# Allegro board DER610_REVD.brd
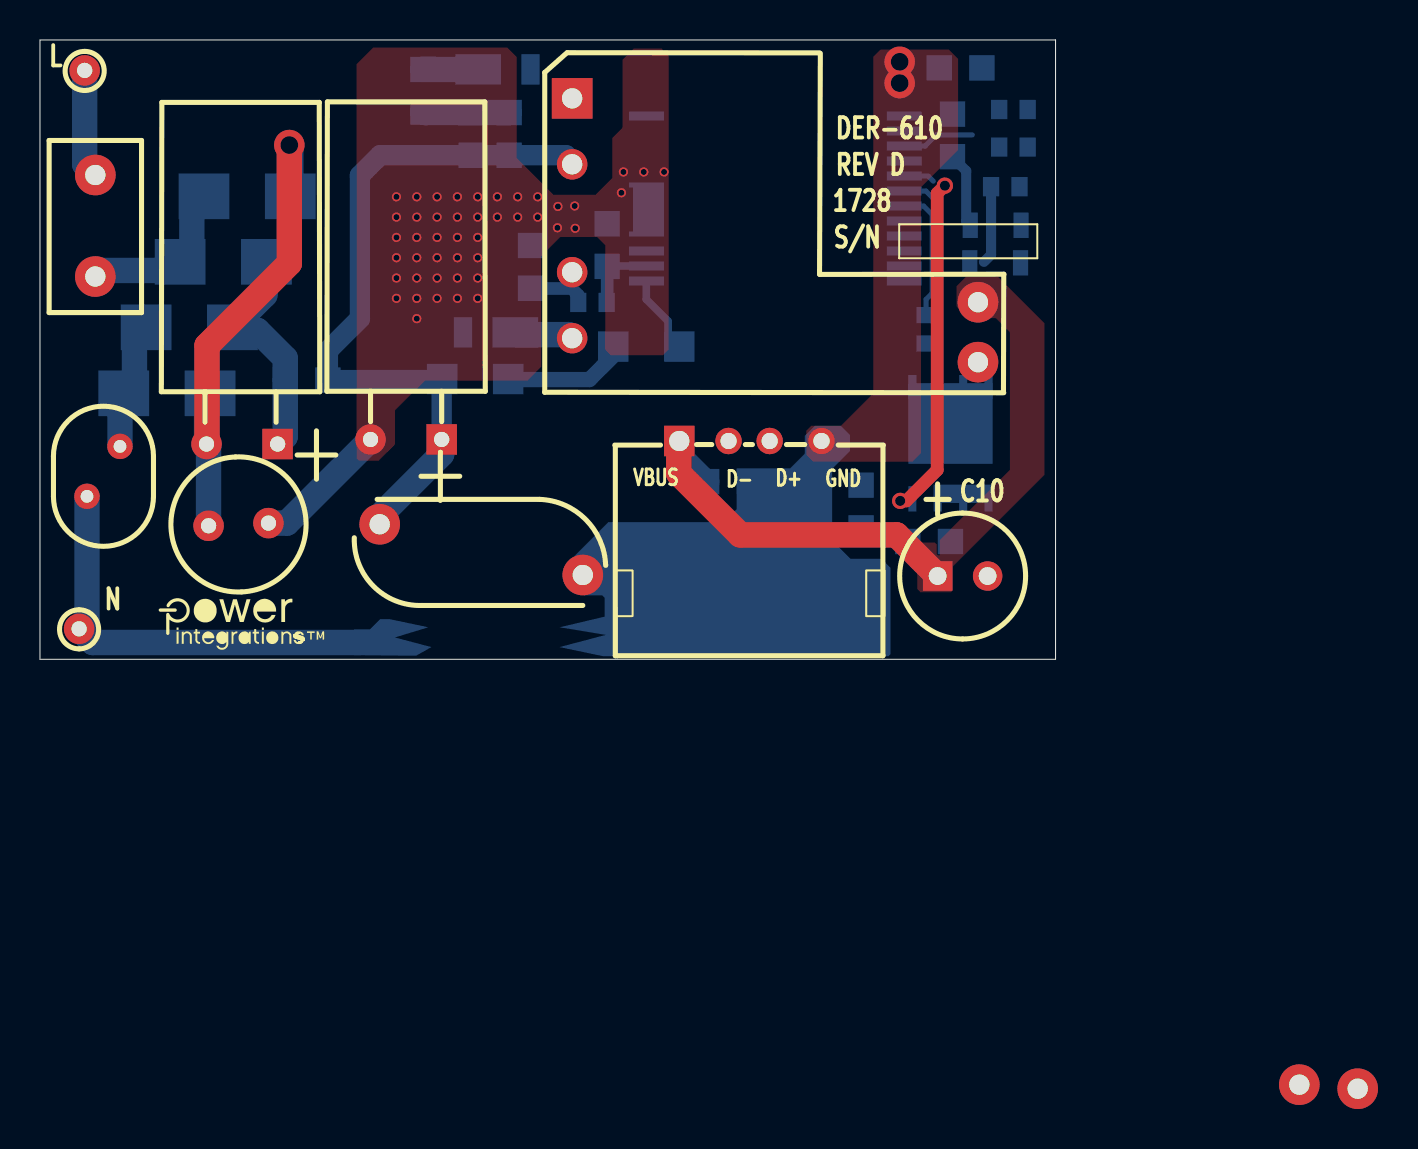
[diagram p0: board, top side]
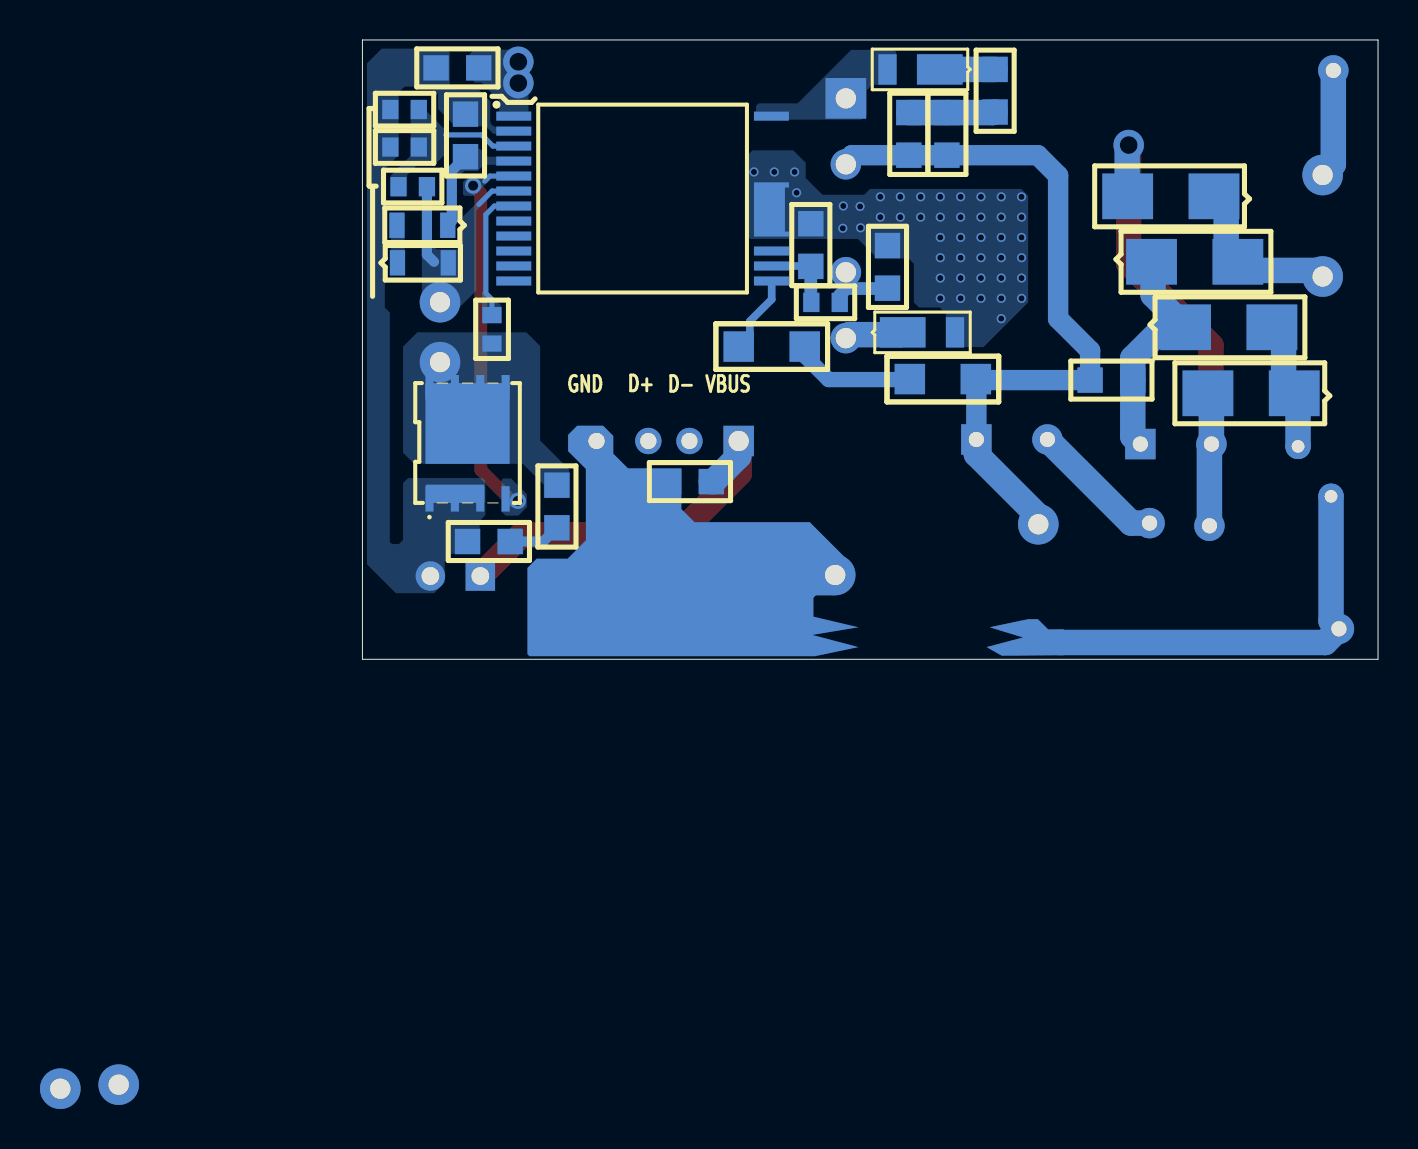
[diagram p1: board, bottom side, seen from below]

Outline 50.8 x 30.99 mm; copper layers: TOP, BOTTOM. Coordinates in mm from the lower left corner of the outline.
Outline path: 0,30.99 0,0 50.8,0 50.8,30.99 0,30.99

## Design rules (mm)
constraint set DEFAULT: min track width 0.508

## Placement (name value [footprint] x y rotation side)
C1  8.2 uF  [PIPOLCAPCLYD320LS140030]  10.11 10.77 180 top
C2  8.2 uF  [PIPOLCAPCLYD320LS140030]  18.31 11 180 bottom
C3  1 nF  [PISMC0805]  23.47 27.36 270 bottom
C4  22 uF  [PISMC0805]  24.54 18.57 90 bottom
C5  4.7 uF  [PISMC0805]  28.37 21.79 270 bottom
C6  2.2 uF  [PISMC0805]  45.64 27.28 270 bottom
C7  330 pF  [PISMC0603]  49.4 27.51 180 bottom
C8  100 pF  [PINPYCAPRAD500X220LS400040]  16.99 6.76 0 top
C9  1.5 nF  [PISMC0805]  43.41 5.89 0 bottom
C10  560 uF  [PI_POLCAP_D248LS098D035]  46.15 4.17 0 top
C12  1 uF  [PISMC0805]  33.35 8.89 0 bottom
D1  RS2MA-13-F  [PISMDO214AC12]  11.33 19.89 180 bottom
D2  RS2MA-13-F  [PISMDO214AC12]  9.63 16.61 180 bottom
D3  RS2MA-13-F  [PISMDO214AC12]  8.2 23.16 0 bottom
D4  RS2MA-13-F  [PISMDO214AC12]  4.19 13.31 0 bottom
D5  DFLR1600-7  [PISMDDFLR120012]  21.89 29.51 180 bottom
D6  DFLR1200-7  [PISMDDFLR120012]  23.8 16.36 0 bottom
D7  BAV19WS  [PISMSOD323]  49.05 19.84 180 bottom
D8  BAV19WS  [PISMSOD323]  46.53 21.72 0 bottom
F1  3.15 A  [PI_RST_MICROFUSE]  2.77 19.15 90 top
J1  PCB Terminal 30 AWG  [PI_HOLE_30AWG]  2.24 29.46 0 top
J2  PCB Terminal 30 AWG  [PI_HOLE_30AWG]  1.96 1.52 0 top
J3  CON4  [PI_USB_4P_GOLDCONN]  31.98 10.92 0 top
L1  4.7 uH  [PISMR0805]  12.27 13.97 0 bottom
L2  100 uH  [PI_CHOKE_365HX275LS118D030]  8.43 6.68 2.5 top
NOREF  -  []  -219.41 -144.7 0 top
NOREF#2  -  []  0.03 0.03 0 top
NOREF#3  -  []  5.38 2.95 0 top
NOREF#4  -  []  -141.59 54.31 0 top
NOREF#5  -  []  0.03 0.03 90 top
Q1  SI7370DP-T1-E3  [PISMPQFN5X6B]  47.45 8.03 180 bottom
R1  200 k  [PISMR0805]  21.56 27.36 270 bottom
R2  30  [PISMR0805]  19.15 29.51 270 bottom
R3  26.7 k  [PISMR0603]  26.92 17.86 0 bottom
R5  2.00 M  [PISMR1206]  31.98 15.65 180 bottom
R6  47  [PISMR0603]  44.32 15.8 90 bottom
R7  20  [PISMR0805]  41.07 6.58 90 bottom
R8  100 k  [PISMR0603]  47.57 23.65 0 bottom
R9  34 k  [PISMR0603]  47.98 25.63 0 bottom
R12  1.50 M  [PISMR1206]  20.12 14.02 0 bottom
R13  0.015  [PISMR0805]  44.98 29.59 0 bottom
RT1  10  [PI_RAD_276DX197T_LS100D025]  3.17 8.15 90 top
T1  EE1621  [PI_BOBBIN_EE1621_8P]  26.62 28.07 0 top
U1  INN3162C  [PI_IC_INSOP_24D]  43.23 27.18 180 bottom

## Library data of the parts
C1 C2 = CAP POL: alternate symbols: (pipolcapclyd320ls140030575h)
C3-C9 C12 = CAP NP
C10 = CAP POL
D1-D8 = DIODE
F1 = FUSE: alternate symbols: (pirstmicrofusehoz)
J1 J2 = TERM_1Pin
J3 = CON4_USB_1
L1 L2 = INDUCTOR
Q1 = FET_N_SGD_123_4_5678
R1-R3 R5-R9 R12 R13 = R
RT1 = THERMISTOR
T1 = BEE16_8P/GENERIC
U1 = DEV_Inno3CE

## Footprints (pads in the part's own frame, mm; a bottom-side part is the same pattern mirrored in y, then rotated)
PI_BOBBIN_EE1621_8P
  rect 2.032x2.032 hole 1.016: 1(0,0)
  round 1.524 hole 1.016: 2(0,-3.3) 3(0,-8.7) 4(0,-12)
  round 2.032 hole 1.016: 5(20.3,-13.2) 6(20.3,-10.2) 7(36.373,-49.352) 8(39.294,-49.555)
PI_CHOKE_365HX275LS118D030
  round 1.524 hole 0.762: 1(0,0) 2(2.997,0)
PI_HOLE_30AWG
  round 1.524 hole 0.762: 1(0,0)
PI_IC_INSOP_24D
  rect 1.75x0.45 smd: 1(0,0) 2(0,-0.75) 3(0,-1.5) 4(0,-2.25) 5(0,-3) 6(0,-3.75) 7(0,-4.5) 8(0,-5.25) 9(0,-6) 10(0,-6.75) 11(0,-7.5) 12(0,-8.25) 13(12.89,-8.25) 14(12.89,-7.5) 15(12.89,-6.75) 24(12.89,0)
  custom 0.438x0.438 smd: 16(12.89,-4.67)
PI_POLCAP_D248LS098D035
  rect 1.473x1.473 hole 0.889: 1(-1.25,0)
  round 1.473 hole 0.889: 2(1.25,0)
PI_RAD_276DX197T_LS100D025
  round 1.27 hole 0.635: 1(0,0.825) 2(2.5,-0.825)
PI_RST_MICROFUSE
  round 2.032 hole 1.016: 1(0,0) 2(5.08,0)
PI_USB_4P_GOLDCONN
  rect 1.524x1.524 hole 1.016: 1(0,0)
  round 1.321 hole 0.813: 2(2.464,0) 3(4.521,0) 4(7.112,0)
PINPYCAPRAD500X220LS400040
  round 2.032 hole 1.016: 1(0,0) 2(10.16,-2.54)
PIPOLCAPCLYD320LS140030
  rect 1.524x1.524 hole 0.762: 1(-1.778,0)
  round 1.524 hole 0.762: 2(1.778,0)
PISMC0603
  rect 0.813x0.965 smd: 1(0,0) 2(1.422,0)
PISMC0805
  rect 1.27x1.27 smd: 1(0,0) 2(2.134,0)
PISMDDFLR120012
  rect 2.286x1.524 smd: 1(-0.025,0)
  rect 0.914x1.524 smd: 2(-2.642,0)
PISMDO214AC12
  rect 2.54x2.286 smd: 1(0,0) 2(4.318,0)
PISMPQFN5X6B
  rect 0.406x1.27 smd: 1(0,0) 2(1.27,0) 3(2.54,0) 4(3.81,0)
  rect 0.406x1.219 smd: 5(3.81,5.588) 6(2.54,5.588) 7(1.27,5.588) 8(0,5.588)
PISMR0603
  rect 0.813x0.965 smd: 1(0,0) 2(1.422,0)
PISMR0805
  rect 1.27x1.27 smd: 1(0,0) 2(2.134,0)
PISMR1206
  rect 1.524x1.524 smd: 1(0,0) 2(3.302,0)
PISMSOD323
  rect 0.762x1.27 smd: 1(0,0) 2(2.54,0)

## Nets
D: Q1.5 Q1.6 Q1.7 Q1.8 R6.1 R7.2 T1.5
NC8: U1.8
NC9: U1.9
NC10: U1.10
NC11: U1.11
NC12: U1.12
NC15: U1.15
S: C6.1 C7.1 C9.2 C10.2 Q1.1(S) Q1.2 Q1.3 R9.2 R13.2 U1.2
N2609146: C2.1 C3.2 C8.1 L1.2 R1.2 R12.1 T1.2
N2609210: C1.1 D1.1 D2.1 L1.1
N2609274: C8.2 C12.2 J3.4 R13.1 U1.1
N2609316: C3.1 R1.1 R2.2
N2609336: C10.1 C12.1 D7.2 J3.1(VBUS) R8.1 T1.6 U1.6
N2609430: D5.1 R2.1
N2609434: D5.2 T1.1 U1.24
N2609584: C4.1 R3.1 T1.3
N2609600: D1.2 D3.1 F1.1
N2609604: D2.2 D4.1 RT1.2
N2609612: C7.2 R8.2 R9.1 U1.3
N2609632: D6.1 T1.4
N2609750: C9.1 R7.1
N2609770: F1.2 J1.1
N2609868: C2.2 C4.2 C5.1 D6.2 L2.2 U1.16
N2609876: C1.2 D3.2 D4.2 L2.1
N2609984: Q1.4 U1.5
N2610014: J2.1 RT1.1
N2610090: C6.2 D8.1 U1.4
N2610148: R6.2 U1.7
N2610260: C5.2 R3.2 U1.14
N2616533: R5.1 U1.13(VPIN)
N2616648: R5.2 R12.2
N2624391: D7.1 D8.2

Pads without a net: J3 2 3; T1 7 8

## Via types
v1: diameter 0.457, hole 0.305, TOP to BOTTOM, 45 vias
v2: diameter 1.524, hole 0.889, TOP to BOTTOM, 3 vias
v3: diameter 0.813, hole 0.508, TOP to BOTTOM, 2 vias

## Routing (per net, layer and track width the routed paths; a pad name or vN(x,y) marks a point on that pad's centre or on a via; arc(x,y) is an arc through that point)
S: length 0.1
  BOTTOM w0.305: C10.2 47.35,4.22
N2609146: length 36.5
  BOTTOM w1.016: 20.09,14 20.07,13.97 L1.2 14.4,15.44 16,17.04 16,24.21 17.02,25.22 R1.2 C3.2 26.32,25.22 26.62,24.92 T1.2 ; 20.09,14 C2.1 ; 20.09,14 R12.1
  BOTTOM w1.27: C8.1 16.99,7.16 20.09,10.26 C2.1
N2609210: length 11.7
  BOTTOM w1.27: C1.1 12.27,11.15 L1.1 12.27,15.06 10.87,16.46 9.78,16.46 D2.1 11.25,18.24 11.25,19.81 D1.1
N2609274:
  vias: v2(43,29.9) v2(43,28.83)
N2609316: length 4.3
  BOTTOM w1.27: C3.1 R1.1 19.28,27.36 R2.2
N2609336: length 25.3
  TOP w1.27: J3.1 31.95,10.9 31.95,9.3 35.03,6.22 42.84,6.22 C10.1
  BOTTOM w0.254: U1.6 44.31,23.43 44.98,22.76
  BOTTOM w0.508: R8.1 47.57,20.24 47.22,19.89
  BOTTOM w1.27: C12.1 33.25,8.89 31.98,10.16 J3.1
N2609430: length 2.8
  BOTTOM w1.27: D5.1 R2.1
N2609434: length 0.2
  BOTTOM w0.508: 26.62,28.22 T1.1
N2609584: length 3.7
  BOTTOM w0.635: 26.59,18.55 26.59,19.34 T1.3 ; 26.59,18.55 24.55,18.55 C4.1 ; 26.59,18.55 26.92,18.22 R3.1
N2609600: length 8.3
  BOTTOM w1.27: F1.1 3.07,19.46 6.58,19.46 7.59,20.47 7.59,22.56 D3.1
N2609604: length 6.5
  BOTTOM w1.27: RT1.2 4,13.12 D4.1 4.72,13.84 4.72,16.03 D2.2
N2609612: length 3.6
  BOTTOM w0.254: U1.3 44.27,25.68 44.83,26.24 46.63,26.24
N2609632: length 3
  BOTTOM w1.27: D6.1 23.89,16.24 26.44,16.24 T1.4
N2609750: length 2.6
  BOTTOM w0.508: R7.1 41.76,5.89 C9.1
N2609770: length 5.5
  BOTTOM w1.27: J1.1 2.24,24.77 F1.2
N2609868: length 6.9
  TOP w0.305: C2.2 16.59,11.05
  BOTTOM w1.27: C2.2 12.35,6.81 L2.2
  vias: v1(17.83,23.14) v1(17.83,22.12) v1(17.83,21.11) v1(17.83,20.09) v1(17.83,19.08) v1(17.83,18.06) v1(18.85,23.14) v1(18.85,22.12) v1(18.85,21.11) v1(18.85,20.09) v1(18.85,19.08) v1(18.85,18.06) v1(18.85,17.04) v1(19.86,23.14) v1(19.86,22.12) v1(19.86,21.11) v1(19.86,20.09) v1(19.86,19.08) v1(19.86,18.06) v1(20.88,23.14) v1(20.88,22.12) v1(20.88,21.11) v1(20.88,20.09) v1(20.88,19.08) v1(20.88,18.06) v1(21.89,23.14) v1(21.89,22.12) v1(21.89,21.11) v1(21.89,20.09) v1(21.89,19.08) v1(21.89,18.06) v1(22.88,23.14) v1(22.88,22.12) v1(23.89,23.14) v1(23.89,22.12) v1(24.89,23.14) v1(24.89,22.12) v1(25.91,22.66) v1(25.88,21.59) v1(26.75,22.68) v1(26.77,21.56) v1(29.08,23.34) v1(29.18,24.38) v1(30.2,24.38) v1(31.22,24.38)
N2609876: length 26
  TOP w1.27: v2(12.47,25.73) 12.47,19.81 8.36,15.7 8.36,10.79 C1.2
  BOTTOM w1.27: L2.1 8.43,10.67 C1.2 8.33,13.13 D4.2 ; v2(12.47,25.73) 12.55,25.65 12.55,23.19 D3.2
N2609984: length 18.4
  TOP w0.635: v3(45.26,23.7) 44.88,23.31 44.88,9.47 43.33,7.92 v3(43.03,7.92)
  BOTTOM w0.254: 44.68,23.92 44.43,24.18 U1.5
N2610014: length 21.1
  BOTTOM w1.27: RT1.1 2.35,1.92 J2.1 2.64,0.84 15.95,0.84
N2610090: length 3.8
  BOTTOM w0.508: C6.2 45.64,25.12 46.33,24.43 46.33,21.92 D8.1
N2610148: length 6.7
  BOTTOM w0.254: U1.7 44.2,22.68 44.63,22.25 44.63,18.31 44.32,18.01 R6.2
N2610260: length 3.8
  BOTTOM w0.381: C5.2 28.39,19.68 U1.14
  BOTTOM w0.635: R3.2 28.37,17.88 C5.2
N2616533: length 4
  BOTTOM w0.381: R5.1 31.42,16.21 31.42,16.92 30.33,18.01 30.33,18.91 U1.13
N2616648: length 6.2
  BOTTOM w0.762: R5.2 28.68,15.19 27.48,14 23.44,14 R12.2

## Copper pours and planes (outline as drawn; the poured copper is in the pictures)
D on BOTTOM (solid shape): 47.65,9.78 43.43,9.78 43.43,13.82 47.65,13.82
D on BOTTOM: 48.77,10.34 48.77,15.65 48.06,16.36 42.6,16.36 41.91,15.67 41.91,10.95 40.46,9.5 40.46,8.1 40.49,8.08 41.71,8.08 41.73,8.1 41.73,8.74 42.77,9.78 48.21,9.78
S on BOTTOM (solid shape): 47.62,7.82 44.7,7.82 44.7,8.74 47.62,8.74
S on BOTTOM: 50.57,4.75 49.12,3.3 47.22,3.3 46.69,3.84 46.69,4.93 46.33,5.28 45.01,5.28 44.93,5.36 44.93,6.93 44.65,7.21 44.65,8.92 44.81,9.07 48.51,9.07 48.77,8.81 48.77,5.97 48.97,5.77 49.33,5.77 49.43,5.87 49.43,17.35 49.68,17.6 49.68,24.54 48.98,25.23 48.98,28.36 48.69,28.65 47.37,28.65 47.02,28.3 47.02,27.53 46.13,26.64 44.6,26.64 44.25,26.29 42.47,26.29 42.44,26.31 42.44,26.57 42.49,26.62 44.15,26.62 44.4,26.87 44.4,27.91 44.98,28.5 46.13,28.5 46.43,28.8 46.43,30.35 46.63,30.56 49.83,30.56 50.57,29.82
N2609274 on BOTTOM (solid shape): 40.51,11.23 40.51,10.41 39.62,9.52 39.62,5.94 40.54,5.03 42.09,5.03 42.54,4.57 42.54,0.25 42.44,0.15 28.17,0.15 25.98,0.61 28.3,1.22 25.98,1.6 28.24,2.13 28.24,3.07 28.12,3.2 27.2,3.2 26.52,3.89 26.52,4.95 28.42,6.86 34.19,6.86 34.85,7.52 34.85,9.55 37.52,9.55 38.25,10.29 38.25,11.18 38.76,11.68 40.06,11.68
N2609274 on TOP: 41.68,30.15 41.68,13.31 40.06,11.68 38.58,11.68 38.33,11.43 38.33,10.24 38.68,9.88 43.64,9.88 44.07,10.31 44.07,23.62 45.92,25.48 45.92,30.05 45.47,30.51 42.04,30.51
N2609274 on BOTTOM: 42.49,27.03 42.49,30.2 42.8,30.51 45.21,30.51 45.52,30.2 45.52,29.21 45.16,28.85 44.86,28.85 43.97,27.97 43.97,27.05 43.94,27.03
N2609336 on TOP: 46.43,17.07 47.8,17.07 48.51,16.36 48.51,9.47 45.01,5.97 45.01,5.21 44.91,5.21 44.86,5.26 44.86,5.74 44.75,5.84 43.59,5.84 43.59,4.7 43.88,4.41 43.88,3.52 44.04,3.35 45.57,3.35 45.67,3.45 45.67,4.65 50.24,9.22 50.24,16.81 47.93,19.13 46.3,19.13 45.85,18.67 45.85,17.65
N2609336 on BOTTOM: 47.62,17.14 46.41,17.14 45.11,18.44 45.11,22.45 44.83,22.73 44.83,22.91 44.88,22.96 44.96,22.96 45.77,22.15 45.77,20.68 45.94,20.51 47.09,20.51 47.31,20.73 47.65,20.73 47.83,20.55 47.83,17.35
N2609434 on BOTTOM: 31.12,27 25.83,27 25.58,27.25 25.58,28.46 25.3,28.74 24.17,28.74 24.1,28.8 24.1,30.4 24.19,30.49 26.35,30.49 29.03,27.81 30.99,27.81 31.12,27.69
N2609612 on BOTTOM: 46.48,26.09 46.61,25.96 46.61,25.32 47.1,24.83 47.97,24.83 48.56,24.23 48.56,23.19 48.59,23.16 49.38,23.16 49.38,24.21 48.39,25.2 48.39,27.79 48.21,27.97 47.73,27.97 47.65,27.89 47.65,27.48 46.48,26.31
N2609868 on TOP: 31.12,30.56 29.69,30.56 29.13,30 29.13,26.59 28.63,26.09 28.63,24.08 27.79,23.24 25.68,23.24 23.85,25.07 23.85,30.12 23.37,30.61 16.66,30.61 15.84,29.78 15.84,10.05 15.95,9.93 16.94,9.93 17.75,10.74 17.75,12.45 19.25,13.94 24.38,13.94 25.07,14.63 25.07,20.17 26.04,21.13 27.86,21.13 28.27,20.73 28.27,15.49 28.55,15.21 31.17,15.21 31.45,15.49 31.45,30.2 31.12,30.53
N2609868 on BOTTOM: 31.39,21.03 26.01,21.03 25.17,20.19 25.17,20.07 25.16,20.05 23.48,20.05 23.22,19.79 23.22,17.86 22.96,17.6 21.92,17.6 21.62,17.3 21.62,15.7 21.54,15.62 19.74,15.62 17.5,17.86 17.5,23.19 17.84,23.53 25.41,23.53 25.7,23.24 27.79,23.24 28.63,24.08 28.63,24.84 29.25,25.46 31.29,25.46 31.46,25.29 31.46,21.1
N2609984 on BOTTOM: 45.21,23.19 44.32,24.08 44.32,24.21 44.4,24.28 44.5,24.28 44.68,24.1 45.54,24.1 45.77,23.88 45.77,23.27 45.69,23.19
N2609984 on BOTTOM: 42.57,8.25 42.57,7.62 43,7.19 43.64,7.19 43.84,7.39 43.84,8.97 43.76,9.04 43.36,9.04
N2610014 on BOTTOM (solid shape): 19.43,1.6 17.75,1.09 19.58,0.61 18.82,0.18 15.72,0.2 15.72,1.5 16.5,1.5 17.01,2.01 17.5,2.01
N2610090 on BOTTOM: 42.47,25.1 42.47,24.79 42.52,24.74 44.73,24.74 45.03,24.43 45.69,24.43 46.33,23.8 46.38,23.8 46.56,23.98 46.56,24.61 46.25,24.92 46.25,25.54 44.92,25.54 44.53,25.15 42.52,25.15
N2610148 on BOTTOM: 44.6,18.44 44.73,18.44 44.81,18.36 44.81,17.12 44.53,16.84 43.99,16.84 43.87,16.97 43.87,17.7
N2624391 on BOTTOM: 48.69,22.28 48.69,19.35 48.77,19.28 49.33,19.28 49.38,19.33 49.38,22.17 49.28,22.28

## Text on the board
Ref Des/Silkscreen Bottom: VBUS | D- | D+
Ref Des/Silkscreen Top: GND | L | N | 1728 | S/N | DER-610 | REV D
DIMENSION: 3 SLOTS | PLEASE DELETED THESE PINS | 13   MATERIAL FR4 COPPER 2oz THICKNESS 0.039"
NCLEGEND-1-2: FIGURE | FINISHED_SIZE | 12.0 | 20.0 | 25.0 | 30.0 | 32.0 | 35.0 | 40.0 | DRILL CHART: TOP to BOTTOM | ALL UNITS ARE IN MILS | PLATED | QTY | 45 | 2 | 8 | 3 | 13
